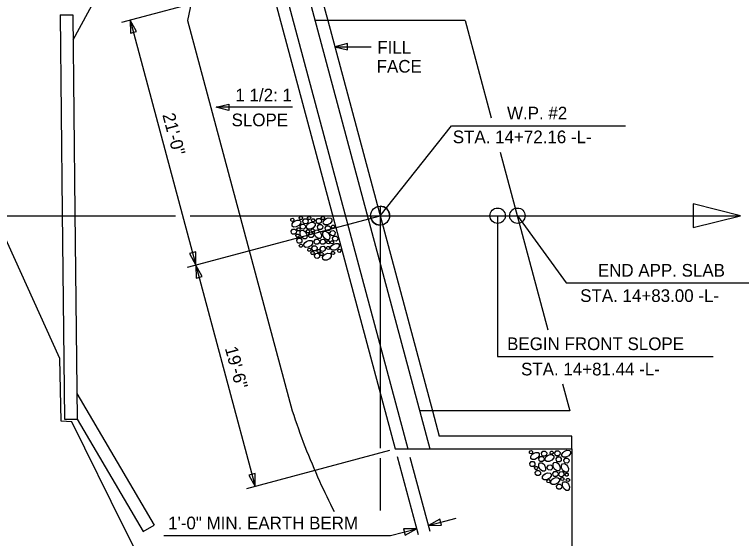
# Model space of a CAD drawing. Extents: x 471 to 2034, y -623 to 126.
# Drawn here: x 704.3 to 761.7, y -46.5 to -5.1 of the extents above; entities that cross this region are included whole.
import ezdxf

# ---------------------------------------------------------------- set-up
doc = ezdxf.new("R2010")
doc.units = 0
for name, color, linetype in [('Arrowhead Terminators CELL', 7, 'Continuous'), ('Auto Dimensioning', 7, 'Continuous'), ('Dimension Lines', 7, 'Continuous'), ('Exist Hydro Stream or Body of Water', 7, 'Continuous'), ('Exist Structure Major Bridge Seam', 7, 'Continuous'), ('Mis Object Lines', 7, 'Continuous'), ('Mis Object Lines Hidden', 7, 'Continuous'), ('Mis Work Point CELL', 7, 'Continuous'), ('Miscellaneous Lines CELL', 7, 'Continuous'), ('Prop Horizontal Alignment', 7, 'Continuous'), ('Sup Concrete Girder Lines', 7, 'Continuous'), ('Text', 7, 'Continuous'), ('User Information Notes', 7, 'Continuous')]:
    doc.layers.add(name, color=color, linetype=linetype)

msp = doc.modelspace()

# ---------------------------------------------------------------- linework, layer by layer
at = {"layer": 'Arrowhead Terminators CELL'}
for points in [[(713.427, -5.555), (713.444, -6.585), (713.927, -6.456)], [(713.427, -5.555), (713.444, -6.585), (713.927, -6.456)], [(729.579, -7.67), (730.579, -7.92), (730.579, -7.42)], [(720.208, -12.446), (721.208, -12.196), (721.208, -12.696)], [(761.613, -21.012), (757.863, -20.075), (757.863, -21.95)], [(718.613, -24.909), (718.595, -23.878), (718.112, -24.007)], [(718.613, -24.909), (718.63, -25.939), (719.113, -25.81)], [(723.301, -42.407), (723.284, -41.376), (722.801, -41.506)], [(736.963, -45.488), (737.993, -45.471), (737.864, -44.988)], [(736.03, -45.738), (734.999, -45.756), (735.128, -46.238)]]:
    msp.add_lwpolyline(points, close=True, dxfattribs=at)
at = {"layer": 'Auto Dimensioning'}
for p, q in [((733.154, -21.512), (733.154, -39.386)), ((733.154, -40.178), (733.154, -44.309))]:
    msp.add_line(p, q, dxfattribs=at)
at = {"layer": 'Dimension Lines'}
for p, q in [((712.752, -5.735), (724.182, -2.673)), ((713.427, -5.555), (718.613, -24.909)), ((729.579, -7.67), (732.458, -7.67)), ((726.23, -12.446), (720.208, -12.446)), ((733.154, -21.012), (738.785, -13.907)), ((738.785, -13.907), (752.518, -13.907)), ((717.938, -25.089), (733.154, -21.012)), ((742.434, -21.012), (742.434, -32.129)), ((743.994, -21.012), (747.838, -26.327)), ((718.613, -24.909), (723.301, -42.407)), ((747.838, -26.327), (763.07, -26.327)), ((742.434, -32.129), (759.447, -32.129)), ((722.622, -42.569), (733.911, -39.544)), ((734.504, -40.045), (736.152, -46.194)), ((735.515, -40.085), (737.085, -45.944)), ((736.963, -45.488), (739.166, -44.898)), ((733.982, -46.287), (736.03, -45.738)), ((716.067, -46.287), (733.982, -46.287))]:
    msp.add_line(p, q, dxfattribs=at)
for centre in [(742.434, -21.012), (743.994, -21.012)]:
    msp.add_circle(centre, 0.606, dxfattribs=at)
at = {"layer": 'Exist Hydro Stream or Body of Water'}
msp.add_lwpolyline([(720.234, -59.995), (712.935, -45.678), (708.822, -37.305), (707.974, -37.243), (707.877, -32.29), (701.705, -18.741)], dxfattribs=at)
at = {"layer": 'Exist Structure Major Bridge Seam'}
for p, q in [((708.907, -7.116), (715.48, 4.866)), ((707.886, -5.155), (708.886, -5.155)), ((709.206, -35.053), (715.317, -45.449)), ((708.234, -37.073), (709.234, -37.073)), ((709.234, -37.073), (714.455, -45.956)), ((714.455, -45.956), (715.317, -45.449))]:
    msp.add_line(p, q, dxfattribs=at)
for points in [[(707.886, -5.155), (708.056, -20.729), (708.234, -37.073)], [(708.886, -5.155), (709.056, -20.729), (709.234, -37.073)]]:
    msp.add_lwpolyline(points, dxfattribs=at)
at = {"layer": 'Mis Object Lines'}
for p, q in [((724.47, -2.596), (734.339, -39.429)), ((725.47, -2.596), (735.339, -39.429)), ((727.22, -2.596), (737.089, -39.429)), ((728.488, -3.596), (729.023, -5.596)), ((739.863, -5.596), (728.023, -5.596)), ((739.863, -5.596), (741.919, -13.269)), ((742.647, -15.982), (746.41, -30.029)), ((747.556, -34.303), (748.125, -36.429)), ((748.125, -36.429), (736.285, -36.429)), ((737.285, -36.429), (737.821, -38.429)), ((748.285, -38.429), (737.821, -38.429)), ((748.285, -39.429), (748.285, -38.429)), ((734.339, -39.429), (748.285, -39.429))]:
    msp.add_line(p, q, dxfattribs=at)
at = {"layer": 'Mis Object Lines Hidden'}
msp.add_line((729.023, -5.596), (737.285, -36.429), dxfattribs=at)
at = {"layer": 'Mis Work Point CELL'}
for p, q in [((733.154, -20.262), (733.154, -21.012)), ((732.404, -21.012), (733.154, -21.012)), ((733.154, -21.012), (733.154, -21.762)), ((733.154, -21.012), (733.904, -21.012)), ((733.904, -21.012), (733.904, -21.012)), ((733.154, -21.762), (733.154, -21.762))]:
    msp.add_line(p, q, dxfattribs=at)
msp.add_circle((733.154, -21.012), 0.75, dxfattribs=at)
for start, end in [(359.99697, 89.99893), (180.00107, 270.00303)]:
    msp.add_arc((733.154, -21.012), 0.75, start, end, dxfattribs=at)
at = {"layer": 'Miscellaneous Lines CELL'}
for points in [[(726.101, -21.32), (726.168, -21.224), (726.276, -21.218), (726.35, -21.296), (726.339, -21.404), (726.273, -21.459), (726.167, -21.451), (726.117, -21.403), (726.101, -21.32)], [(726.77, -21.173), (726.837, -21.078), (726.944, -21.072), (727.019, -21.149), (727.008, -21.257), (726.942, -21.313), (726.836, -21.305), (726.786, -21.257), (726.77, -21.173)], [(727.433, -21.173), (727.5, -21.078), (727.607, -21.072), (727.682, -21.149), (727.671, -21.257), (727.605, -21.313), (727.499, -21.305), (727.449, -21.257), (727.433, -21.173)], [(728.102, -21.398), (728.214, -21.239), (728.393, -21.228), (728.518, -21.357), (728.5, -21.538), (728.389, -21.63), (728.212, -21.617), (728.129, -21.537), (728.102, -21.398)], [(728.513, -21.173), (728.58, -21.078), (728.687, -21.072), (728.762, -21.149), (728.751, -21.257), (728.685, -21.313), (728.579, -21.305), (728.529, -21.257), (728.513, -21.173)], [(728.854, -21.271), (729.064, -21.188), (729.256, -21.204), (729.348, -21.291), (729.345, -21.447), (729.206, -21.625), (728.991, -21.732), (728.789, -21.736), (728.675, -21.655), (728.664, -21.494), (728.757, -21.35), (728.863, -21.265)], [(726.391, -21.443), (726.601, -21.36), (726.794, -21.376), (726.885, -21.463), (726.882, -21.619), (726.743, -21.797), (726.529, -21.904), (726.326, -21.908), (726.212, -21.827), (726.202, -21.666), (726.294, -21.522), (726.4, -21.437)], [(726.844, -21.844), (726.956, -21.685), (727.135, -21.674), (727.26, -21.803), (727.242, -21.984), (727.131, -22.076), (726.955, -22.063), (726.871, -21.982), (726.844, -21.844)], [(727.055, -21.422), (727.167, -21.263), (727.346, -21.253), (727.471, -21.382), (727.453, -21.562), (727.342, -21.654), (727.165, -21.641), (727.082, -21.561), (727.055, -21.422)], [(727.53, -21.612), (727.74, -21.529), (727.932, -21.546), (728.024, -21.633), (728.021, -21.789), (727.882, -21.966), (727.667, -22.074), (727.465, -22.077), (727.351, -21.996), (727.34, -21.835), (727.433, -21.691), (727.539, -21.607)], [(727.735, -21.357), (727.802, -21.261), (727.91, -21.255), (727.984, -21.332), (727.973, -21.441), (727.907, -21.496), (727.801, -21.488), (727.751, -21.44), (727.735, -21.357)], [(728.208, -21.875), (728.32, -21.716), (728.499, -21.706), (728.623, -21.835), (728.605, -22.015), (728.494, -22.107), (728.318, -22.094), (728.235, -22.014), (728.208, -21.875)], [(728.82, -21.973), (728.932, -21.813), (729.111, -21.803), (729.236, -21.932), (729.218, -22.113), (729.107, -22.205), (728.93, -22.192), (728.847, -22.111), (728.82, -21.973)], [(729.308, -21.856), (729.375, -21.76), (729.483, -21.754), (729.557, -21.831), (729.547, -21.94), (729.48, -21.995), (729.374, -21.987), (729.324, -21.939), (729.308, -21.856)], [(726.126, -22.244), (726.238, -22.084), (726.417, -22.074), (726.541, -22.203), (726.523, -22.384), (726.413, -22.476), (726.236, -22.463), (726.153, -22.382), (726.126, -22.244)], [(726.587, -22.079), (726.655, -21.984), (726.762, -21.978), (726.837, -22.055), (726.826, -22.163), (726.76, -22.219), (726.654, -22.211), (726.604, -22.163), (726.588, -22.079)], [(727.302, -22.356), (727.385, -22.566), (727.369, -22.759), (727.282, -22.85), (727.125, -22.847), (726.948, -22.708), (726.84, -22.494), (726.837, -22.291), (726.918, -22.177), (727.079, -22.167), (727.223, -22.259), (727.307, -22.365)], [(727.321, -22.23), (727.388, -22.134), (727.496, -22.128), (727.57, -22.205), (727.559, -22.314), (727.493, -22.369), (727.387, -22.361), (727.337, -22.313), (727.321, -22.23)], [(727.503, -22.515), (727.615, -22.356), (727.794, -22.345), (727.919, -22.474), (727.901, -22.655), (727.79, -22.747), (727.614, -22.734), (727.53, -22.654), (727.503, -22.515)], [(727.7, -22.154), (727.767, -22.058), (727.875, -22.052), (727.949, -22.129), (727.938, -22.238), (727.872, -22.293), (727.766, -22.285), (727.716, -22.237), (727.7, -22.154)], [(728.441, -22.329), (728.524, -22.539), (728.507, -22.731), (728.42, -22.823), (728.264, -22.82), (728.087, -22.681), (727.979, -22.466), (727.976, -22.264), (728.057, -22.15), (728.218, -22.14), (728.362, -22.232), (728.446, -22.338)], [(729.105, -22.431), (729.188, -22.641), (729.172, -22.833), (729.085, -22.925), (728.928, -22.922), (728.751, -22.783), (728.644, -22.568), (728.64, -22.366), (728.721, -22.252), (728.882, -22.241), (729.026, -22.334), (729.111, -22.439)], [(729.194, -22.362), (729.306, -22.203), (729.484, -22.193), (729.609, -22.321), (729.591, -22.502), (729.48, -22.594), (729.304, -22.581), (729.221, -22.501), (729.194, -22.362)], [(726.511, -22.57), (726.578, -22.475), (726.685, -22.469), (726.76, -22.546), (726.749, -22.654), (726.683, -22.71), (726.577, -22.702), (726.527, -22.654), (726.511, -22.57)], [(726.568, -22.956), (726.68, -22.796), (726.859, -22.786), (726.983, -22.915), (726.965, -23.096), (726.855, -23.188), (726.678, -23.175), (726.595, -23.094), (726.568, -22.956)], [(727.952, -23.035), (728.064, -22.875), (728.243, -22.865), (728.367, -22.994), (728.349, -23.175), (728.239, -23.266), (728.062, -23.254), (727.979, -23.173), (727.952, -23.035)], [(728.413, -23.041), (728.525, -22.882), (728.704, -22.872), (728.828, -23.001), (728.81, -23.181), (728.699, -23.273), (728.523, -23.26), (728.44, -23.18), (728.413, -23.041)], [(729.389, -22.792), (729.501, -22.632), (729.68, -22.622), (729.805, -22.751), (729.787, -22.932), (729.676, -23.024), (729.499, -23.011), (729.416, -22.93), (729.389, -22.792)], [(726.77, -23.372), (726.837, -23.277), (726.944, -23.271), (727.019, -23.348), (727.008, -23.456), (726.942, -23.511), (726.836, -23.504), (726.786, -23.455), (726.77, -23.372)], [(727.327, -23.049), (727.536, -22.966), (727.729, -22.983), (727.82, -23.07), (727.818, -23.226), (727.679, -23.403), (727.464, -23.511), (727.262, -23.514), (727.148, -23.433), (727.137, -23.272), (727.229, -23.128), (727.335, -23.044)], [(727.77, -23.557), (727.882, -23.398), (728.061, -23.387), (728.186, -23.516), (728.168, -23.697), (728.057, -23.789), (727.88, -23.776), (727.797, -23.696), (727.77, -23.557)], [(728.409, -23.597), (728.521, -23.438), (728.7, -23.427), (728.825, -23.556), (728.807, -23.737), (728.696, -23.829), (728.519, -23.816), (728.436, -23.736), (728.409, -23.597)], [(728.923, -23.091), (728.99, -22.995), (729.097, -22.989), (729.172, -23.066), (729.161, -23.175), (729.095, -23.23), (728.989, -23.222), (728.939, -23.174), (728.923, -23.091)], [(728.923, -23.537), (728.99, -23.441), (729.097, -23.435), (729.172, -23.513), (729.161, -23.621), (729.095, -23.676), (728.989, -23.669), (728.939, -23.62), (728.923, -23.537)], [(729.226, -23.091), (729.293, -22.995), (729.401, -22.989), (729.475, -23.066), (729.465, -23.175), (729.398, -23.23), (729.292, -23.222), (729.242, -23.174), (729.226, -23.091)], [(729.439, -23.282), (729.649, -23.199), (729.841, -23.216), (729.933, -23.303), (729.93, -23.459), (729.791, -23.636), (729.576, -23.744), (729.374, -23.747), (729.26, -23.666), (729.249, -23.505), (729.342, -23.361), (729.447, -23.277)], [(727.442, -23.684), (727.509, -23.588), (727.617, -23.582), (727.691, -23.659), (727.68, -23.768), (727.614, -23.823), (727.508, -23.815), (727.458, -23.767), (727.442, -23.684)], [(727.695, -23.943), (727.762, -23.848), (727.87, -23.842), (727.944, -23.919), (727.933, -24.027), (727.867, -24.083), (727.761, -24.075), (727.711, -24.027), (727.695, -23.943)], [(727.963, -24.15), (728.075, -23.991), (728.254, -23.98), (728.379, -24.109), (728.361, -24.29), (728.25, -24.382), (728.073, -24.369), (727.99, -24.288), (727.963, -24.15)], [(728.174, -23.79), (728.242, -23.695), (728.349, -23.688), (728.423, -23.766), (728.413, -23.874), (728.346, -23.929), (728.24, -23.922), (728.191, -23.873), (728.174, -23.79)], [(728.401, -24.023), (728.468, -23.928), (728.575, -23.922), (728.65, -23.999), (728.639, -24.107), (728.573, -24.163), (728.467, -24.155), (728.417, -24.107), (728.401, -24.023)], [(728.807, -24.055), (729.016, -23.972), (729.209, -23.988), (729.3, -24.075), (729.297, -24.231), (729.158, -24.409), (728.944, -24.516), (728.742, -24.52), (728.628, -24.439), (728.617, -24.278), (728.709, -24.134), (728.815, -24.049)], [(729.306, -23.93), (729.373, -23.834), (729.48, -23.828), (729.555, -23.906), (729.544, -24.014), (729.478, -24.069), (729.372, -24.062), (729.322, -24.013), (729.306, -23.93)], [(729.798, -23.77), (729.866, -23.675), (729.973, -23.669), (730.048, -23.746), (730.037, -23.854), (729.971, -23.909), (729.865, -23.902), (729.815, -23.853), (729.799, -23.77)], [(744.942, -39.676), (745.009, -39.58), (745.117, -39.574), (745.191, -39.651), (745.181, -39.76), (745.114, -39.815), (745.008, -39.807), (744.958, -39.759), (744.942, -39.676)], [(746.943, -39.754), (747.055, -39.595), (747.234, -39.584), (747.359, -39.713), (747.341, -39.894), (747.23, -39.986), (747.054, -39.973), (746.97, -39.893), (746.943, -39.754)], [(747.695, -39.627), (747.905, -39.543), (748.097, -39.56), (748.189, -39.647), (748.186, -39.803), (748.047, -39.981), (747.832, -40.088), (747.63, -40.092), (747.516, -40.011), (747.506, -39.85), (747.598, -39.706), (747.704, -39.621)], [(745.232, -39.799), (745.442, -39.716), (745.635, -39.732), (745.726, -39.819), (745.723, -39.975), (745.584, -40.153), (745.37, -40.26), (745.167, -40.264), (745.054, -40.183), (745.043, -40.022), (745.135, -39.878), (745.241, -39.793)], [(745.685, -40.2), (745.798, -40.04), (745.976, -40.03), (746.101, -40.159), (746.083, -40.34), (745.972, -40.432), (745.796, -40.419), (745.713, -40.338), (745.686, -40.2)], [(745.896, -39.778), (746.008, -39.619), (746.187, -39.609), (746.312, -39.738), (746.294, -39.918), (746.183, -40.01), (746.006, -39.997), (745.923, -39.917), (745.896, -39.778)], [(746.371, -39.968), (746.581, -39.885), (746.773, -39.902), (746.865, -39.989), (746.862, -40.145), (746.723, -40.322), (746.508, -40.43), (746.306, -40.433), (746.192, -40.352), (746.181, -40.191), (746.274, -40.047), (746.38, -39.963)], [(746.576, -39.713), (746.643, -39.617), (746.751, -39.611), (746.825, -39.688), (746.815, -39.797), (746.748, -39.852), (746.642, -39.844), (746.592, -39.796), (746.576, -39.713)], [(747.049, -40.231), (747.161, -40.072), (747.34, -40.062), (747.464, -40.19), (747.446, -40.371), (747.336, -40.463), (747.159, -40.45), (747.076, -40.37), (747.049, -40.231)], [(747.661, -40.329), (747.773, -40.169), (747.952, -40.159), (748.077, -40.288), (748.059, -40.469), (747.948, -40.561), (747.772, -40.548), (747.688, -40.467), (747.661, -40.329)], [(744.967, -40.6), (745.079, -40.44), (745.258, -40.43), (745.382, -40.559), (745.364, -40.74), (745.254, -40.832), (745.077, -40.819), (744.994, -40.738), (744.967, -40.6)], [(746.143, -40.712), (746.226, -40.922), (746.21, -41.114), (746.123, -41.206), (745.966, -41.203), (745.789, -41.064), (745.682, -40.85), (745.678, -40.647), (745.759, -40.533), (745.92, -40.523), (746.064, -40.615), (746.149, -40.721)], [(746.344, -40.871), (746.457, -40.712), (746.635, -40.701), (746.76, -40.83), (746.742, -41.011), (746.631, -41.103), (746.455, -41.09), (746.372, -41.009), (746.345, -40.871)], [(747.282, -40.685), (747.365, -40.895), (747.348, -41.087), (747.261, -41.179), (747.105, -41.176), (746.928, -41.037), (746.82, -40.822), (746.817, -40.62), (746.898, -40.506), (747.059, -40.495), (747.203, -40.588), (747.287, -40.694)], [(747.946, -40.787), (748.029, -40.996), (748.013, -41.189), (747.926, -41.281), (747.769, -41.278), (747.592, -41.139), (747.485, -40.924), (747.481, -40.722), (747.562, -40.608), (747.723, -40.597), (747.867, -40.689), (747.952, -40.795)], [(745.352, -40.926), (745.419, -40.831), (745.527, -40.825), (745.601, -40.902), (745.59, -41.01), (745.524, -41.066), (745.418, -41.058), (745.368, -41.009), (745.352, -40.926)], [(745.409, -41.312), (745.521, -41.152), (745.7, -41.142), (745.824, -41.271), (745.806, -41.452), (745.696, -41.543), (745.519, -41.531), (745.436, -41.45), (745.409, -41.312)], [(746.168, -41.405), (746.377, -41.322), (746.57, -41.339), (746.662, -41.426), (746.659, -41.582), (746.52, -41.759), (746.305, -41.867), (746.103, -41.87), (745.989, -41.789), (745.978, -41.628), (746.071, -41.484), (746.176, -41.4)], [(746.793, -41.39), (746.905, -41.231), (747.084, -41.221), (747.208, -41.35), (747.19, -41.531), (747.08, -41.622), (746.903, -41.61), (746.82, -41.529), (746.793, -41.391)], [(747.254, -41.397), (747.366, -41.238), (747.545, -41.228), (747.669, -41.357), (747.651, -41.537), (747.541, -41.629), (747.364, -41.616), (747.281, -41.536), (747.254, -41.397)], [(746.319, -41.967), (746.386, -41.871), (746.493, -41.865), (746.568, -41.942), (746.557, -42.051), (746.491, -42.106), (746.385, -42.098), (746.335, -42.05), (746.319, -41.967)], [(746.818, -41.78), (747.028, -41.696), (747.22, -41.713), (747.312, -41.8), (747.309, -41.956), (747.17, -42.134), (746.955, -42.241), (746.753, -42.245), (746.639, -42.164), (746.628, -42.003), (746.721, -41.859), (746.827, -41.774)], [(747.417, -41.783), (747.484, -41.687), (747.591, -41.681), (747.666, -41.758), (747.655, -41.867), (747.589, -41.922), (747.483, -41.914), (747.433, -41.866), (747.417, -41.783)], [(747.764, -41.447), (747.831, -41.351), (747.938, -41.345), (748.013, -41.422), (748.002, -41.531), (747.936, -41.586), (747.83, -41.578), (747.78, -41.53), (747.764, -41.447)], [(747.858, -41.862), (747.925, -41.766), (748.033, -41.76), (748.107, -41.837), (748.097, -41.946), (748.03, -42.001), (747.924, -41.993), (747.874, -41.945), (747.858, -41.862)], [(747.093, -42.388), (747.205, -42.228), (747.384, -42.218), (747.508, -42.347), (747.49, -42.528), (747.38, -42.62), (747.203, -42.607), (747.12, -42.526), (747.093, -42.388)], [(748.028, -42.217), (748.111, -42.427), (748.094, -42.619), (748.007, -42.711), (747.851, -42.708), (747.673, -42.569), (747.566, -42.354), (747.562, -42.152), (747.643, -42.038), (747.804, -42.027), (747.948, -42.12), (748.033, -42.226)]]:
    msp.add_lwpolyline(points, dxfattribs=at)
at = {"layer": 'Prop Horizontal Alignment'}
for p, q in [((657.095, -21.012), (717.006, -21.012)), ((718.163, -21.012), (761.613, -21.012))]:
    msp.add_line(p, q, dxfattribs=at)
at = {"layer": 'Sup Concrete Girder Lines'}
for p, q in [((717.959, -5.596), (726.221, -36.429)), ((737.285, -39.429), (748.285, -39.429)), ((748.285, -39.429), (748.285, -64.986))]:
    msp.add_line(p, q, dxfattribs=at)
for centre, radius, start, end in [((740.262, -9.323), 22.612, 90.14614, 170.51266), ((777.095, -19.924), 53.484, 197.97431, 204.36369), ((777.095, -19.924), 53.484, 204.36369, 207.21179)]:
    msp.add_arc(centre, radius, start, end, dxfattribs=at)
at = {"layer": 'User Information Notes'}
msp.add_line((733.154, -21.012), (733.154, -21.012), dxfattribs=at)
msp.add_line((733.154, -21.012), (733.154, -21.012), dxfattribs=at)

# ---------------------------------------------------------------- texts
at = {"layer": 'Dimension Lines'}
for s, p in [('FILL', (732.933, -8.212)), ('FACE', (732.882, -9.712))]:
    msp.add_text(s, height=1, dxfattribs=at).set_placement(p)
for s, p in [('21\'-0"', (715.952, -13.045)), ('19\'-6"', (720.892, -31.483))]:
    msp.add_text(s, height=1, rotation=285, dxfattribs=at).set_placement(p)
at = {"layer": 'Text'}
for s, p in [('1 1/2: 1', (721.729, -11.981)), ('W.P. #2', (743.175, -13.407)), ('SLOPE', (721.428, -13.946)), ('STA. 14+72.16 -L-', (738.894, -15.287)), ('END APP. SLAB', (750.349, -25.827)), ('STA. 14+83.00 -L-', (748.952, -27.827)), ('BEGIN FRONT SLOPE', (743.183, -31.629)), ('STA. 14+81.44 -L-', (744.283, -33.629)), ('1\'-0" MIN. EARTH BERM', (716.419, -45.787))]:
    msp.add_text(s, height=1, dxfattribs=at).set_placement(p)

doc.saveas('drawing.dxf')
